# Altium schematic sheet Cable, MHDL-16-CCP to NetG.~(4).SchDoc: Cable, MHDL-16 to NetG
size B; ApprovedBy: Hans Thomas; CheckedBy: Hans Thomas; Author: Hans Thomas; DrawnBy: Hans Thomas; Engineer: Hans Thomas; Organization: MBARI; DocumentNumber: 100221139; Revision: A; SheetNumber: 1; SheetTotal: 1; PageSetup: Record=PageOptions¦CenterHorizontal=True¦CenterVertical=True¦PrintScale=0.94¦XCorrection=1.00¦YCorrection=1.00¦PrintKind=0¦BorderSize=5000000¦LeftOffset=0¦BottomOffset=0¦Orientation=2¦PaperLength=4318¦PaperWidth=2794¦Scale=100¦PaperSource=15¦PrintQuality=-3¦MediaType=1¦DitherType=0¦PrintScaleMode=1¦PaperKind=Letter (8.5 x 11 in)¦PaperIndex=1
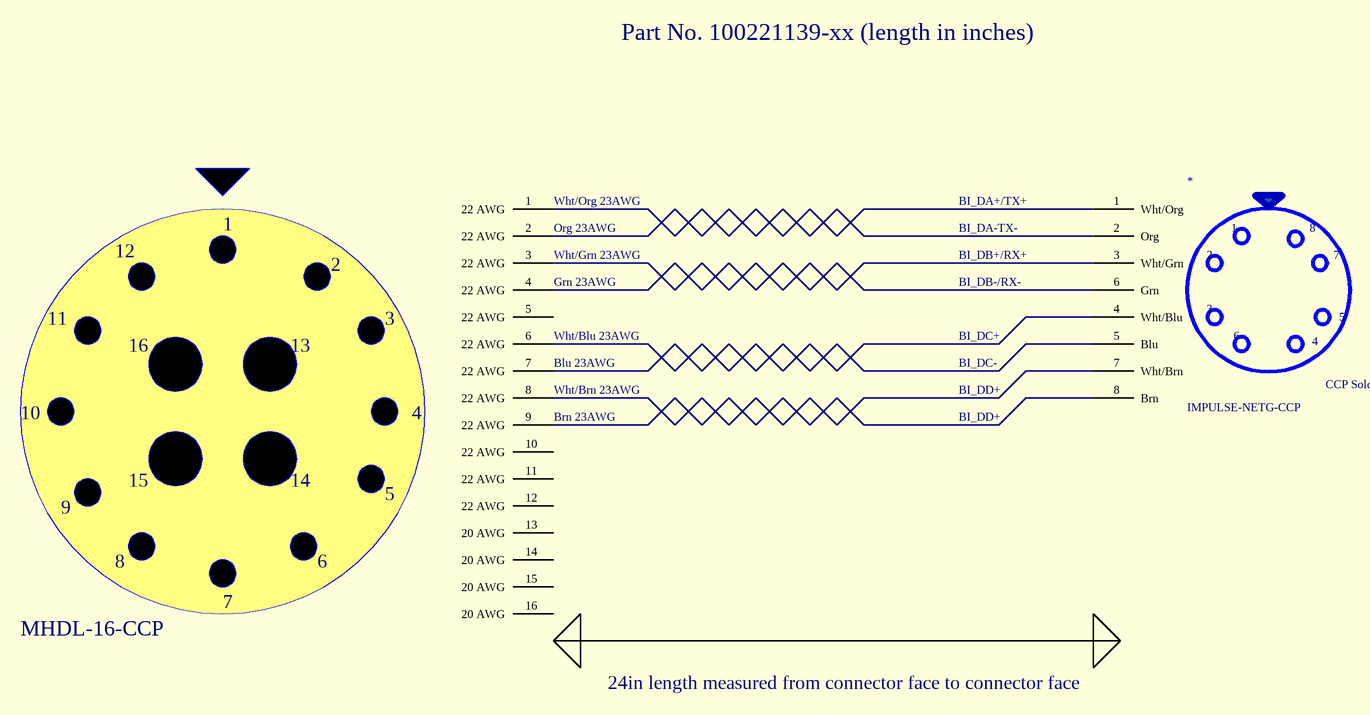
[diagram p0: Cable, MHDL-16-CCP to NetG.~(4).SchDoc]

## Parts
*  IMPULSE-NETG-CCP
J?  MHDL-16-CCP

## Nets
Net*_1: *.1(Wht/Org) J?.1(22_AWG)
Net*_2: *.2(Org) J?.2(22_AWG)
Net*_3: *.3(Wht/Grn) J?.3(22_AWG)
Net*_4: *.4(Wht/Blu) J?.6(22_AWG)
Net*_5: *.5(Blu) J?.7(22_AWG)
Net*_6: *.6(Grn) J?.4(22_AWG)
Net*_7: *.7(Wht/Brn) J?.8(22_AWG)
Net*_8: *.8(Brn) J?.9(22_AWG)

Not connected (* = marked no-connect by the designer): J? 5(22_AWG) 10(22_AWG) 11(22_AWG) 12(22_AWG) 13(20_AWG) 14(20_AWG) 15(20_AWG) 16(20_AWG)

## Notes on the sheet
- Part No. 100221139-xx (length in inches)
- (near J?) Wht/Grn 23AWG
- (near J?) Wht/Org 23AWG
- (near J?) Org 23AWG
- BI_DA+/TX+
- BI_DA-TX-
- BI_DB+/RX+
- (near J?) Grn 23AWG
- BI_DB-/RX-
- (near J?) Wht/Blu 23AWG
- (near J?) Blu 23AWG
- (near J?) Wht/Brn 23AWG
- BI_DC+
- BI_DC-
- BI_DD+
- (near J?) Brn 23AWG
- 24in length measured from connector face to connector face

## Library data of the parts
J? = MHDL-16-CCP-SOLDER: Impulse MHDL 16 CCP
